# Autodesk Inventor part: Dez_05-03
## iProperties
Created: 2005-12
Part Number: Dez_05-03
Document SubType Name: Modeling
Designer: W. Holzwarth
Author: W. Holzwarth
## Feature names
1. Drehung1 [Revolution]
